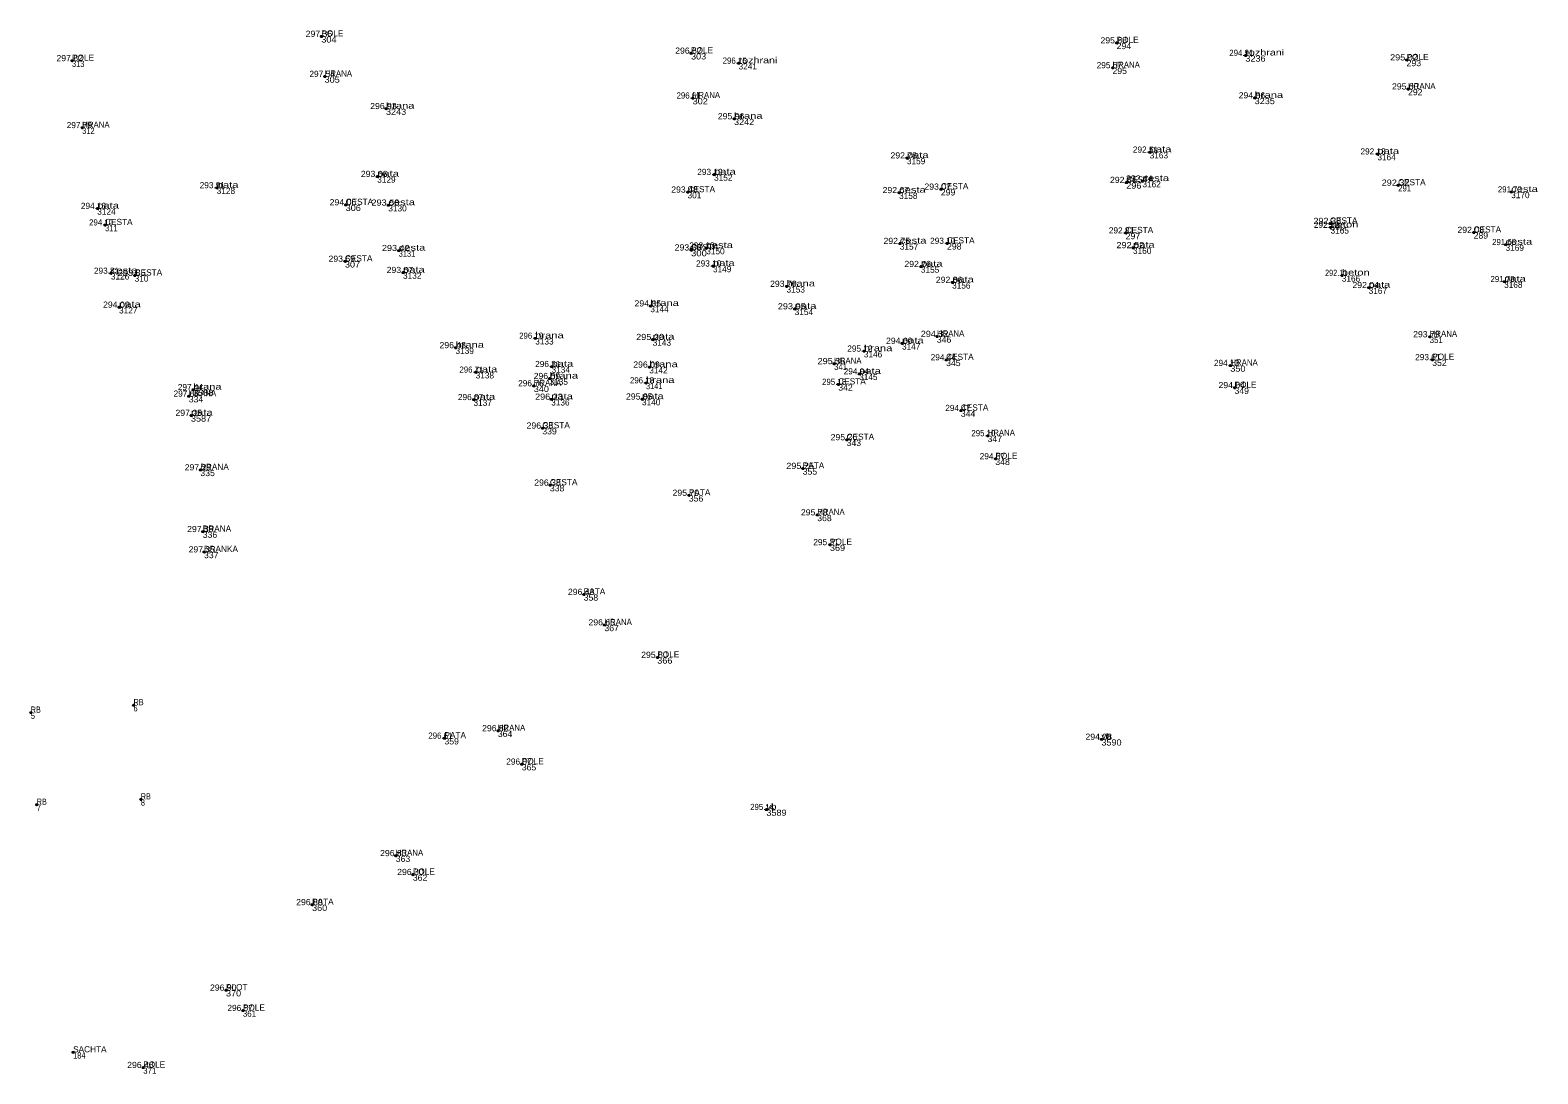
# Model space of a CAD drawing. Extents: x -565336 to -561834, y -1146819 to -1145270.
# Drawn here: x -563748.6 to -563665.5, y -1145716.8 to -1145659.3 of the extents above; entities that cross this region are included whole.
import ezdxf
from ezdxf.enums import TextEntityAlignment as Align

# ---------------------------------------------------------------- set-up
doc = ezdxf.new("R2010")
doc.units = 0
doc.header["$LTSCALE"] = 0.14
doc.header["$PDMODE"] = 32
doc.header["$PDSIZE"] = 0.07
for name, color, linetype in [('40', 7, 'Continuous'), ('43', 7, 'Continuous'), ('44', 7, 'Continuous'), ('45', 7, 'Continuous')]:
    doc.layers.add(name, color=color, linetype=linetype)

msp = doc.modelspace()

# ---------------------------------------------------------------- linework, layer by layer
at = {"layer": '40'}
for p in [(-563732.52, -1145659.62), (-563688.72, -1145659.98), (-563746.25, -1145660.96), (-563712.16, -1145660.55), (-563709.54, -1145661.1), (-563681.63, -1145660.67), (-563672.75, -1145660.92), (-563732.34, -1145661.83), (-563688.95, -1145661.35), (-563672.67, -1145662.52), (-563728.96, -1145663.6), (-563712.07, -1145663.02), (-563681.12, -1145663.01), (-563709.79, -1145664.16), (-563745.69, -1145664.65), (-563686.9, -1145666), (-563674.36, -1145666.1), (-563700.27, -1145666.32), (-563729.44, -1145667.34), (-563710.89, -1145667.23), (-563688.19, -1145667.67), (-563687.3, -1145667.59), (-563673.22, -1145667.82), (-563738.28, -1145667.96), (-563712.35, -1145668.2), (-563700.7, -1145668.23), (-563698.4, -1145668.04), (-563666.99, -1145668.19), (-563744.86, -1145669.1), (-563731.18, -1145668.9), (-563728.83, -1145668.92), (-563744.43, -1145670.01), (-563676.97, -1145669.93), (-563676.94, -1145670.14), (-563700.66, -1145671.03), (-563698.06, -1145671.02), (-563688.22, -1145670.45), (-563669.06, -1145670.42), (-563667.3, -1145671.09), (-563728.26, -1145671.42), (-563712.16, -1145671.39), (-563711.32, -1145671.28), (-563687.82, -1145671.26), (-563744.11, -1145672.67), (-563742.8, -1145672.79), (-563731.22, -1145672.01), (-563728.02, -1145672.63), (-563710.95, -1145672.27), (-563699.5, -1145672.3), (-563676.32, -1145672.79), (-563706.9, -1145673.39), (-563697.78, -1145673.17), (-563674.84, -1145673.46), (-563667.38, -1145673.13), (-563714.4, -1145674.47), (-563743.66, -1145674.54), (-563706.45, -1145674.63), (-563725.13, -1145676.77), (-563720.74, -1145676.25), (-563714.27, -1145676.32), (-563702.64, -1145676.96), (-563700.54, -1145676.53), (-563698.62, -1145676.15), (-563671.48, -1145676.17), (-563704.28, -1145677.65), (-563698.11, -1145677.44), (-563682.46, -1145677.75), (-563671.34, -1145677.43), (-563724.02, -1145678.12), (-563719.95, -1145678.47), (-563719.84, -1145677.81), (-563714.46, -1145677.84), (-563702.9, -1145678.21), (-563739.82, -1145679.44), (-563739.58, -1145679.08), (-563720.82, -1145678.87), (-563714.64, -1145678.71), (-563704.05, -1145678.79), (-563682.23, -1145678.97), (-563724.14, -1145679.63), (-563719.86, -1145679.61), (-563714.86, -1145679.6), (-563697.3, -1145680.23), (-563739.7, -1145680.5), (-563720.35, -1145681.2), (-563703.59, -1145681.84), (-563695.83, -1145681.62), (-563739.18, -1145683.5), (-563706.01, -1145683.42), (-563695.4, -1145682.89), (-563719.93, -1145684.34), (-563712.28, -1145684.9), (-563705.21, -1145685.98), (-563739.05, -1145686.9), (-563704.51, -1145687.62), (-563738.98, -1145688.02), (-563718.07, -1145690.36), (-563716.93, -1145692.04), (-563714.02, -1145693.83), (-563748.52, -1145696.87), (-563742.86, -1145696.46), (-563725.74, -1145698.28), (-563722.8, -1145697.87), (-563689.56, -1145698.34), (-563721.48, -1145699.71), (-563742.46, -1145701.65), (-563748.19, -1145701.94), (-563708.01, -1145702.21), (-563728.42, -1145704.75), (-563727.48, -1145705.79), (-563733.03, -1145707.45), (-563737.77, -1145712.16), (-563736.84, -1145713.28), (-563746.19, -1145715.58), (-563742.33, -1145716.42)]:
    msp.add_point(p, dxfattribs=at)

# ---------------------------------------------------------------- texts
at = {"layer": '43'}
for s, width, p in [('304', 1.1, (-563732.52, -1145659.96)), ('294', 1.05, (-563688.72, -1145660.32)), ('313', 0.9, (-563746.25, -1145661.3)), ('303', 1.1, (-563712.16, -1145660.89)), ('3236', 1.1, (-563681.63, -1145661.01)), ('293', 1.05, (-563672.75, -1145661.26)), ('305', 1.1, (-563732.34, -1145662.17)), ('295', 1.05, (-563688.95, -1145661.69)), ('292', 1.05, (-563672.67, -1145662.86)), ('3243', 1.1, (-563728.96, -1145663.94)), ('302', 1.1, (-563712.07, -1145663.36)), ('3235', 1.1, (-563681.12, -1145663.35)), ('3242', 1.1, (-563709.79, -1145664.5)), ('312', 0.9, (-563745.69, -1145664.99)), ('296', 1.1, (-563688.19, -1145668.01)), ('299', 1.05, (-563698.4, -1145668.38)), ('291', 0.95, (-563673.22, -1145668.16)), ('306', 1.1, (-563731.18, -1145669.24)), ('311', 0.8, (-563744.43, -1145670.35)), ('290', 1.1, (-563676.97, -1145670.27)), ('298', 1.05, (-563698.06, -1145671.36)), ('297', 1.05, (-563688.22, -1145670.79)), ('289', 1.05, (-563669.06, -1145670.76)), ('3131', 0.9, (-563728.26, -1145671.76)), ('300', 1.15, (-563712.16, -1145671.73)), ('307', 1.1, (-563731.22, -1145672.35)), ('346', 1.05, (-563698.62, -1145676.49)), ('351', 0.95, (-563671.48, -1145676.51)), ('341', 0.95, (-563704.28, -1145677.99)), ('345', 1.05, (-563698.11, -1145677.78)), ('350', 1.1, (-563682.46, -1145678.09)), ('352', 1.05, (-563671.34, -1145677.77)), ('3588', 1.1, (-563739.58, -1145679.42)), ('340', 1.1, (-563720.82, -1145679.21)), ('3141', 0.9, (-563714.64, -1145679.05)), ('342', 1.05, (-563704.05, -1145679.13)), ('349', 1.05, (-563682.23, -1145679.31)), ('334', 1.05, (-563739.82, -1145679.78)), ('344', 1.05, (-563697.3, -1145680.57)), ('3587', 1.1, (-563739.7, -1145680.84)), ('339', 1.05, (-563720.35, -1145681.54)), ('343', 1.05, (-563703.59, -1145682.18)), ('347', 1.05, (-563695.83, -1145681.96)), ('335', 1.05, (-563739.18, -1145683.84)), ('355', 1.05, (-563706.01, -1145683.76)), ('348', 1.05, (-563695.4, -1145683.23)), ('338', 1.05, (-563719.93, -1145684.68)), ('356', 1.05, (-563712.28, -1145685.24)), ('368', 1.05, (-563705.21, -1145686.32)), ('336', 1.05, (-563739.05, -1145687.24)), ('369', 1.1, (-563704.51, -1145687.96)), ('337', 1.05, (-563738.98, -1145688.36)), ('358', 1.05, (-563718.07, -1145690.7)), ('367', 1.05, (-563716.93, -1145692.38)), ('366', 1.1, (-563714.02, -1145694.17)), ('6', 0.85, (-563742.86, -1145696.8)), ('5', 0.75, (-563748.52, -1145697.21)), ('359', 1.05, (-563725.74, -1145698.62)), ('364', 1.05, (-563722.8, -1145698.21)), ('3590', 1.1, (-563689.56, -1145698.68)), ('365', 1.05, (-563721.48, -1145700.05)), ('8', 0.75, (-563742.46, -1145701.99)), ('7', 0.75, (-563748.19, -1145702.28)), ('3589', 1.1, (-563708.01, -1145702.55)), ('363', 1.05, (-563728.42, -1145705.09)), ('362', 1.05, (-563727.48, -1145706.13)), ('360', 1.1, (-563733.03, -1145707.79)), ('370', 1.1, (-563737.77, -1145712.5)), ('361', 0.95, (-563736.84, -1145713.62)), ('184', 0.9, (-563746.19, -1145715.92)), ('371', 0.95, (-563742.33, -1145716.76))]:
    msp.add_text(s, height=0.34, dxfattribs=dict(at, width=width)).set_placement(p)
for s, p in [('3241', (-563709.54, -1145661.44)), ('3163', (-563686.9, -1145666.34)), ('3164', (-563674.36, -1145666.44)), ('3159', (-563700.27, -1145666.66)), ('3129', (-563729.44, -1145667.68)), ('3152', (-563710.89, -1145667.57)), ('3162', (-563687.3, -1145667.93)), ('3128', (-563738.28, -1145668.3)), ('301', (-563712.35, -1145668.54)), ('3158', (-563700.7, -1145668.57)), ('3170', (-563666.99, -1145668.53)), ('3124', (-563744.86, -1145669.44)), ('3130', (-563728.83, -1145669.26)), ('3165', (-563676.94, -1145670.48)), ('3157', (-563700.66, -1145671.37)), ('3169', (-563667.3, -1145671.43)), ('3150', (-563711.32, -1145671.62)), ('3160', (-563687.82, -1145671.6)), ('3126', (-563744.11, -1145673.01)), ('3132', (-563728.02, -1145672.97)), ('3149', (-563710.95, -1145672.61)), ('3155', (-563699.5, -1145672.64)), ('310', (-563742.8, -1145673.13)), ('3153', (-563706.9, -1145673.73)), ('3156', (-563697.78, -1145673.51)), ('3166', (-563676.32, -1145673.13)), ('3167', (-563674.84, -1145673.8)), ('3168', (-563667.38, -1145673.47)), ('3127', (-563743.66, -1145674.88)), ('3144', (-563714.4, -1145674.81)), ('3154', (-563706.45, -1145674.97)), ('3139', (-563725.13, -1145677.11)), ('3133', (-563720.74, -1145676.59)), ('3143', (-563714.27, -1145676.66)), ('3147', (-563700.54, -1145676.87)), ('3146', (-563702.64, -1145677.3)), ('3138', (-563724.02, -1145678.46)), ('3135', (-563719.95, -1145678.81)), ('3134', (-563719.84, -1145678.15)), ('3142', (-563714.46, -1145678.18)), ('3145', (-563702.9, -1145678.55)), ('3137', (-563724.14, -1145679.97)), ('3136', (-563719.86, -1145679.95)), ('3140', (-563714.86, -1145679.94))]:
    msp.add_text(s, height=0.34, dxfattribs=at).set_placement(p)
at = {"layer": '44'}
for s, width, p in [('297.36', 1.05, (-563732.65, -1145659.644)), ('296.62', 1.05, (-563712.3005, -1145660.574)), ('295.68', 1.05, (-563688.8805, -1145660.004)), ('297.82', 1.05, (-563746.377, -1145660.984)), ('296.15', 0.95, (-563709.7555, -1145661.124)), ('294.91', 0.95, (-563681.855, -1145660.694)), ('295.02', 1.1, (-563672.8945, -1145660.944)), ('296.61', 0.95, (-563712.295, -1145663.044)), ('294.86', 1.05, (-563681.27, -1145663.034)), ('295.00', 1.05, (-563672.824, -1145662.544)), ('296.93', 1.05, (-563729.098, -1145663.624)), ('295.96', 1.05, (-563709.9545, -1145664.184)), ('292.78', 1.05, (-563700.4445, -1145666.344)), ('293.66', 1.05, (-563729.6125, -1145667.364)), ('293.07', 1.05, (-563698.5755, -1145668.064)), ('292.84', 1.05, (-563688.355, -1145667.694)), ('292.44', 1.05, (-563687.47, -1145667.614)), ('292.32', 1.1, (-563673.358, -1145667.844)), ('294.06', 1.05, (-563731.33, -1145668.924)), ('293.58', 1.1, (-563728.9895, -1145668.944)), ('293.48', 1.05, (-563712.5185, -1145668.224)), ('292.67', 1.05, (-563700.8785, -1145668.254)), ('291.73', 0.95, (-563667.0665, -1145668.214)), ('294.10', 0.95, (-563744.6495, -1145670.034)), ('292.38', 1.1, (-563677.119, -1145669.954)), ('292.08', 1.05, (-563669.221, -1145670.444)), ('293.42', 1.1, (-563728.418, -1145671.444)), ('293.60', 1.05, (-563712.3275, -1145671.414)), ('292.75', 1.05, (-563700.829, -1145671.054)), ('292.52', 1.1, (-563687.966, -1145671.284)), ('291.68', 0.95, (-563667.3815, -1145671.114)), ('293.69', 1.05, (-563731.3925, -1145672.034)), ('293.85', 1.1, (-563742.958, -1145672.814)), ('293.57', 1.05, (-563728.1915, -1145672.654)), ('292.76', 1.05, (-563699.6785, -1145672.324)), ('292.11', 0.85, (-563676.6295, -1145672.814)), ('293.70', 1.05, (-563707.0755, -1145673.414)), ('292.86', 1.05, (-563697.945, -1145673.194)), ('292.04', 1.05, (-563675.005, -1145673.484)), ('291.78', 0.95, (-563667.47, -1145673.154)), ('294.09', 1.05, (-563743.81, -1145674.564)), ('294.85', 1.05, (-563714.5405, -1145674.494)), ('293.95', 1.1, (-563706.6135, -1145674.654)), ('296.19', 0.95, (-563720.965, -1145676.274)), ('295.20', 1.1, (-563714.4145, -1145676.344)), ('294.32', 1.1, (-563698.743, -1145676.174)), ('293.79', 1.05, (-563671.661, -1145676.194)), ('296.48', 1.05, (-563725.281, -1145676.794)), ('294.60', 1.05, (-563700.69, -1145676.554)), ('296.09', 1.05, (-563714.61, -1145677.864)), ('295.38', 1.1, (-563704.4235, -1145677.674)), ('296.71', 0.95, (-563724.253, -1145678.144)), ('296.59', 1.05, (-563720.096, -1145678.494)), ('296.18', 0.95, (-563714.861, -1145678.734)), ('295.18', 0.95, (-563704.2805, -1145678.814)), ('296.23', 1.1, (-563719.983, -1145679.634)), ('295.85', 1.05, (-563715.01, -1145679.624)), ('294.04', 1.05, (-563682.38, -1145678.994)), ('297.25', 1.05, (-563739.823, -1145680.524)), ('296.38', 1.05, (-563720.484, -1145681.224)), ('295.26', 1.05, (-563703.74, -1145681.864)), ('295.10', 0.95, (-563696.059, -1145681.644)), ('297.29', 1.05, (-563739.3125, -1145683.524)), ('295.25', 1.1, (-563706.1505, -1145683.444)), ('296.38', 1.05, (-563720.064, -1145684.364)), ('295.70', 1.05, (-563712.4475, -1145684.924)), ('295.78', 1.05, (-563705.379, -1145686.004)), ('297.39', 1.05, (-563739.18, -1145686.924)), ('297.35', 1.05, (-563739.1005, -1145688.044)), ('296.43', 1.05, (-563718.208, -1145690.384)), ('296.65', 1.05, (-563717.076, -1145692.064)), ('295.80', 1.05, (-563714.174, -1145693.854)), ('296.82', 1.05, (-563722.935, -1145697.894)), ('296.61', 0.95, (-563725.965, -1145698.304)), ('294.08', 1.05, (-563689.706, -1145698.364)), ('295.14', 0.95, (-563708.2445, -1145702.234)), ('296.83', 1.05, (-563728.5525, -1145704.774)), ('296.30', 1.05, (-563727.6125, -1145705.814)), ('296.80', 1.05, (-563733.1745, -1145707.474)), ('296.90', 1.05, (-563737.92, -1145712.184)), ('296.48', 1.05, (-563742.481, -1145716.444))]:
    msp.add_text(s, height=0.34, dxfattribs=dict(at, width=width)).set_placement(p, align=Align.CENTER)
for s, p in [('295.67', (-563689.123, -1145661.374)), ('297.54', (-563732.478, -1145661.854)), ('297.79', (-563745.8455, -1145664.674)), ('292.51', (-563687.1305, -1145666.024)), ('292.18', (-563674.596, -1145666.124)), ('293.12', (-563711.1175, -1145667.254)), ('293.91', (-563738.5225, -1145667.984)), ('294.13', (-563745.0675, -1145669.124)), ('292.81', (-563688.4545, -1145670.474)), ('292.12', (-563677.165, -1145670.164)), ('293.10', (-563711.557, -1145671.304)), ('293.10', (-563698.297, -1145671.044)), ('293.81', (-563744.347, -1145672.694)), ('293.10', (-563711.187, -1145672.294)), ('295.12', (-563702.8595, -1145676.984)), ('296.31', (-563720.0475, -1145677.834)), ('294.44', (-563698.265, -1145677.464)), ('294.13', (-563682.6675, -1145677.774)), ('293.61', (-563671.5825, -1145677.454)), ('296.76', (-563720.9835, -1145678.894)), ('294.94', (-563703.055, -1145678.234)), ('297.60', (-563739.962, -1145679.464)), ('297.44', (-563739.727, -1145679.104)), ('296.67', (-563724.3035, -1145679.654)), ('294.47', (-563697.4635, -1145680.254)), ('294.67', (-563695.5635, -1145682.914)), ('295.31', (-563704.727, -1145687.644)), ('296.07', (-563721.638, -1145699.734)), ('296.57', (-563736.994, -1145713.304))]:
    msp.add_text(s, height=0.34, dxfattribs=at).set_placement(p, align=Align.CENTER)
at = {"layer": '45'}
for s, p in [('POLE', (-563732.52, -1145659.62)), ('POLE', (-563712.16, -1145660.55)), ('POLE', (-563688.72, -1145659.98)), ('POLE', (-563746.25, -1145660.96)), ('POLE', (-563672.75, -1145660.92)), ('CESTA', (-563698.4, -1145668.04)), ('CESTA', (-563688.19, -1145667.67)), ('CESTA', (-563673.22, -1145667.82)), ('CESTA', (-563731.18, -1145668.9)), ('CESTA', (-563712.35, -1145668.2)), ('CESTA', (-563744.43, -1145670.01)), ('CESTA', (-563688.22, -1145670.45)), ('CESTA', (-563676.97, -1145669.93)), ('CESTA', (-563669.06, -1145670.42)), ('CESTA', (-563712.16, -1145671.39)), ('CESTA', (-563698.06, -1145671.02)), ('CESTA', (-563731.22, -1145672.01)), ('CESTA', (-563742.8, -1145672.79)), ('CESTA', (-563698.11, -1145677.44)), ('POLE', (-563671.34, -1145677.43)), ('CESTA', (-563704.05, -1145678.79)), ('POLE', (-563682.23, -1145678.97)), ('CESTA', (-563697.3, -1145680.23)), ('CESTA', (-563720.35, -1145681.2)), ('CESTA', (-563703.59, -1145681.84)), ('POLE', (-563695.4, -1145682.89)), ('BRANA', (-563739.18, -1145683.5)), ('PATA', (-563706.01, -1145683.42)), ('CESTA', (-563719.93, -1145684.34)), ('PATA', (-563712.28, -1145684.9)), ('BRANA', (-563739.05, -1145686.9)), ('BRANKA', (-563738.98, -1145688.02)), ('POLE', (-563704.51, -1145687.62)), ('PATA', (-563718.07, -1145690.36)), ('POLE', (-563714.02, -1145693.83)), ('PATA', (-563725.74, -1145698.28)), ('POLE', (-563721.48, -1145699.71)), ('POLE', (-563727.48, -1145705.79)), ('PATA', (-563733.03, -1145707.45)), ('PLOT', (-563737.77, -1145712.16)), ('POLE', (-563736.84, -1145713.28)), ('SACHTA', (-563746.19, -1145715.58)), ('POLE', (-563742.33, -1145716.42))]:
    msp.add_text(s, height=0.34, dxfattribs=at).set_placement(p)
for s, width, p in [('rozhrani', 1.3, (-563681.63, -1145660.67)), ('rozhrani', 1.3, (-563709.54, -1145661.1)), ('HRANA', 0.95, (-563688.95, -1145661.35)), ('HRANA', 0.95, (-563732.34, -1145661.83)), ('HRANA', 0.95, (-563712.07, -1145663.02)), ('hrana', 1.35, (-563681.12, -1145663.01)), ('HRANA', 0.95, (-563672.67, -1145662.52)), ('hrana', 1.35, (-563728.96, -1145663.6)), ('HRANA', 0.95, (-563745.69, -1145664.65)), ('hrana', 1.35, (-563709.79, -1145664.16)), ('pata', 1.35, (-563700.27, -1145666.32)), ('pata', 1.35, (-563686.9, -1145666)), ('pata', 1.35, (-563674.36, -1145666.1)), ('pata', 1.35, (-563710.89, -1145667.23)), ('pata', 1.35, (-563738.28, -1145667.96)), ('pata', 1.35, (-563729.44, -1145667.34)), ('cesta', 1.35, (-563687.3, -1145667.59)), ('cesta', 1.35, (-563728.83, -1145668.92)), ('cesta', 1.35, (-563700.7, -1145668.23)), ('cesta', 1.35, (-563666.99, -1145668.19)), ('pata', 1.35, (-563744.86, -1145669.1)), ('beton', 1.35, (-563676.94, -1145670.14)), ('cesta', 1.35, (-563728.26, -1145671.42)), ('cesta', 1.35, (-563711.32, -1145671.28)), ('cesta', 1.35, (-563700.66, -1145671.03)), ('pata', 1.35, (-563687.82, -1145671.26)), ('cesta', 1.35, (-563667.3, -1145671.09)), ('cesta', 1.35, (-563744.11, -1145672.67)), ('pata', 1.35, (-563728.02, -1145672.63)), ('pata', 1.35, (-563710.95, -1145672.27)), ('pata', 1.35, (-563699.5, -1145672.3)), ('beton', 1.35, (-563676.32, -1145672.79)), ('hrana', 1.35, (-563706.9, -1145673.39)), ('pata', 1.35, (-563697.78, -1145673.17)), ('pata', 1.35, (-563674.84, -1145673.46)), ('pata', 1.35, (-563667.38, -1145673.13)), ('pata', 1.35, (-563743.66, -1145674.54)), ('hrana', 1.35, (-563714.4, -1145674.47)), ('pata', 1.35, (-563706.45, -1145674.63)), ('hrana', 1.35, (-563720.74, -1145676.25)), ('pata', 1.35, (-563714.27, -1145676.32)), ('HRANA', 0.95, (-563698.62, -1145676.15)), ('HRANA', 0.95, (-563671.48, -1145676.17)), ('hrana', 1.35, (-563725.13, -1145676.77)), ('hrana', 1.35, (-563702.64, -1145676.96)), ('pata', 1.35, (-563700.54, -1145676.53)), ('pata', 1.35, (-563719.84, -1145677.81)), ('hrana', 1.35, (-563714.46, -1145677.84)), ('HRANA', 0.95, (-563704.28, -1145677.65)), ('HRANA', 0.95, (-563682.46, -1145677.75)), ('pata', 1.35, (-563724.02, -1145678.12)), ('HRANA', 0.95, (-563720.82, -1145678.87)), ('hrana', 1.35, (-563719.95, -1145678.47)), ('hrana', 1.35, (-563714.64, -1145678.71)), ('pata', 1.35, (-563702.9, -1145678.21)), ('HRANA', 0.95, (-563739.82, -1145679.44)), ('hrana', 1.35, (-563739.58, -1145679.08)), ('pata', 1.35, (-563724.14, -1145679.63)), ('pata', 1.35, (-563719.86, -1145679.61)), ('pata', 1.35, (-563714.86, -1145679.6)), ('pata', 1.35, (-563739.7, -1145680.5)), ('HRANA', 0.95, (-563695.83, -1145681.62)), ('HRANA', 0.95, (-563705.21, -1145685.98)), ('HRANA', 0.95, (-563716.93, -1145692.04)), ('RB', 0.85, (-563748.52, -1145696.87)), ('RB', 0.85, (-563742.86, -1145696.46)), ('HRANA', 0.95, (-563722.8, -1145697.87)), ('vb', 1.15, (-563689.56, -1145698.34)), ('RB', 0.85, (-563748.19, -1145701.94)), ('RB', 0.85, (-563742.46, -1145701.65)), ('vb', 1.15, (-563708.01, -1145702.21)), ('HRANA', 0.95, (-563728.42, -1145704.75))]:
    msp.add_text(s, height=0.34, dxfattribs=dict(at, width=width)).set_placement(p)

doc.saveas('drawing.dxf')
